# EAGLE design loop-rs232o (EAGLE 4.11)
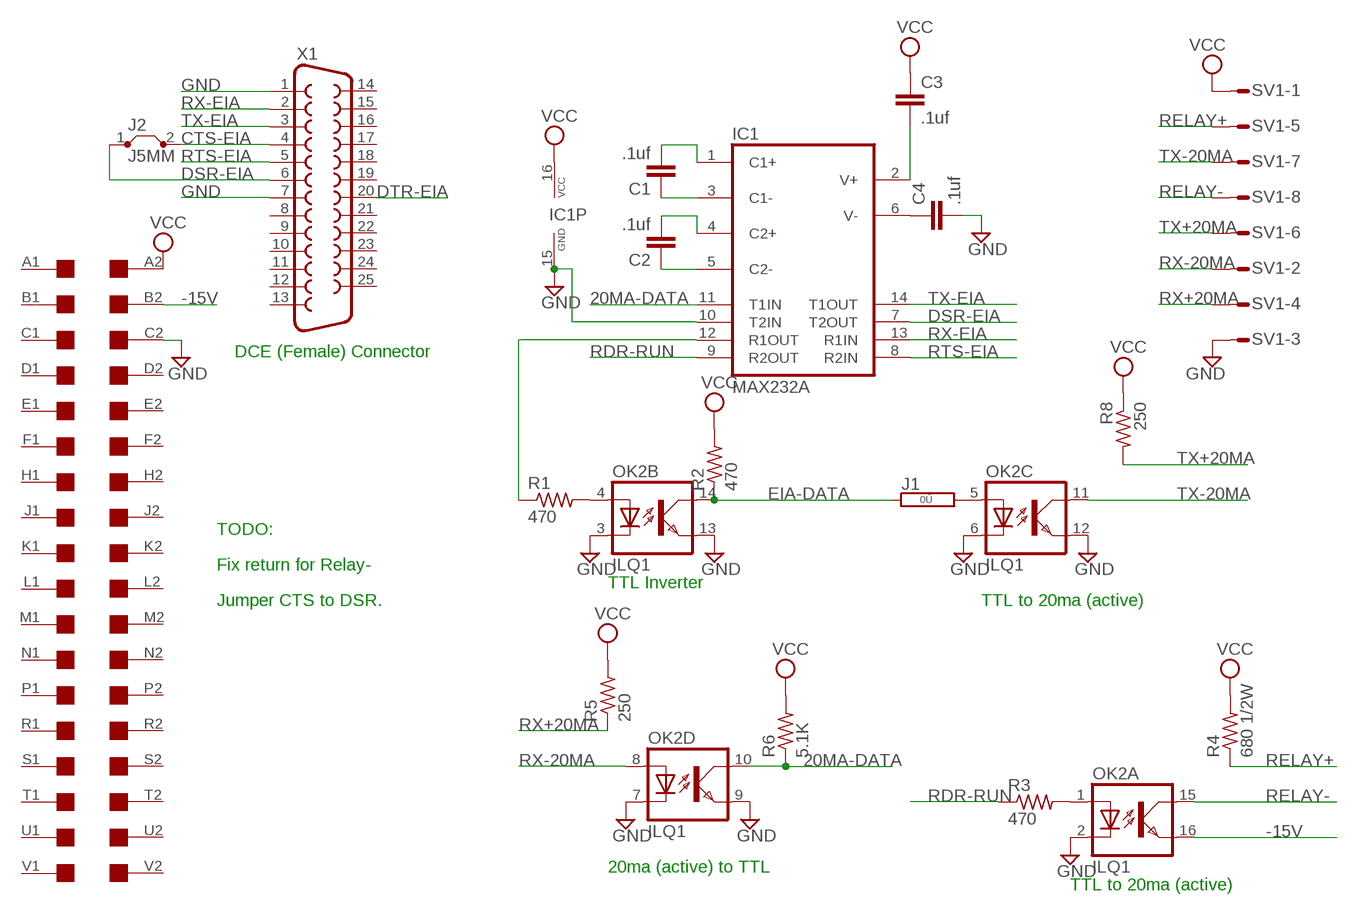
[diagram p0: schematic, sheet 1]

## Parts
C1  .1uf  C-EU050-025X075  [C050-025X075]
C2  .1uf  C-EU050-025X075  [C050-025X075]
C3  .1uf  C-EU050-025X075  [C050-025X075]
C4  .1uf  C-EU050-025X075  [C050-025X075]
IC1  MAX232A  MAX232  [DIL16]
J1  0R  [0R/10]
J2  J5MM  [05]
OK2  ILQ1  [DIL16]
R1  470  R-US_0207/10  [0207/10]
R2  470  R-US_0207/10  [0207/10]
R3  470  R-US_0207/10  [0207/10]
R4  680 1/2W  R-US_0207/10  [0207/10]
R5  250  R-US_0207/10  [0207/10]
R6  5.1K  R-US_0207/10  [0207/10]
R8  250  R-US_0207/10  [0207/10]
SV1  S08P  [S08P]
U$1  DEC-FLIPCHIP  [DEC-FLIPCHIP]
X1  F25H  [F25H]

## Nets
20MA-DATA: IC1.11(T1IN) OK2.10(D:COL) R6.1
-15V: OK2.16(A:EMIT) U$1.B2
CTS-EIA: J2.2 X1.4
DSR-EIA: IC1.7(T2OUT) J2.1 X1.6
DTR-EIA: X1.20
EIA-DATA: J1.1 OK2.14(B:COL) R2.1
GND: C4.2 IC1.10(T2IN) IC1.15(GND) OK2.2(A:C) OK2.3(B:C) OK2.6(C:C) OK2.7(D:C) OK2.9(D:EMIT) OK2.12(C:EMIT) OK2.13(B:EMIT) SV1.3 U$1.C2 X1.1 X1.7
N$1: C2.1 IC1.5(C2-)
N$2: C2.2 IC1.4(C2+)
N$3: C1.2 IC1.1(C1+)
N$4: C1.1 IC1.3(C1-)
N$8: IC1.12(R1OUT) R1.1
N$9: C3.2 IC1.2(V+)
N$10: C4.1 IC1.6(V-)
N$11: OK2.4(B:A) R1.2
N$12: OK2.1(A:A) R3.2
N$15: J1.2 OK2.5(C:A)
RDR-RUN: IC1.9(R2OUT) R3.1
RELAY+: R4.1 SV1.5
RELAY-: OK2.15(A:COL) SV1.8
RTS-EIA: IC1.8(R2IN) X1.5
RX+20MA: R5.1 SV1.4
RX-20MA: OK2.8(D:A) SV1.2
RX-EIA: IC1.13(R1IN) X1.2
TX+20MA: R8.2 SV1.6
TX-20MA: OK2.11(C:COL) SV1.7
TX-EIA: IC1.14(T1OUT) X1.3
VCC: C3.1 IC1.16(VCC) R2.2 R4.2 R5.2 R6.2 R8.1 SV1.1 U$1.A2
Unconnected: U$1.A1 U$1.B1 U$1.C1 U$1.D1 U$1.D2 U$1.E1 U$1.E2 U$1.F1 U$1.F2 U$1.H1 U$1.H2 U$1.J1 U$1.J2 U$1.K1 U$1.K2 U$1.L1 U$1.L2 U$1.M1 U$1.M2 U$1.N1 U$1.N2 U$1.P1 U$1.P2 U$1.R1 U$1.R2 U$1.S1 U$1.S2 U$1.T1 U$1.T2 U$1.U1 U$1.U2 U$1.V1 U$1.V2 X1.8 X1.9 X1.10 X1.11 X1.12 X1.13 X1.14 X1.15 X1.16 X1.17 X1.18 X1.19 X1.21 X1.22 X1.23 X1.24 X1.25

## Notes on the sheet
- DCE (Female) Connector
- TODO:
- Fix return for Relay-
- TTL Inverter
- Jumper CTS to DSR. | TTL to 20ma (active)
- 20ma (active) to TTL
- TTL to 20ma (active)

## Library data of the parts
C1-C4 = rcl:C-EU: CAPACITOR, European symbol
IC1 = maxim:MAX232: RS232 TRANSEIVER
J1 = jumper:0R: Bridge 0R 10mm
J2 = jumper:J: Bridge
OK2 = optocoupler:ILQ1: SIEMENS OPTO COUPLER
R1-R6 R8 = rcl:R-US_: RESISTOR, American symbol
SV1 = con-amp-mt:S08P: AMP MT CONNECTOR
U$1 = con-dec:DEC-FLIPCHIP: DEC Flip-Chip single card fingers
X1 = con-subd:F25: SUB-D

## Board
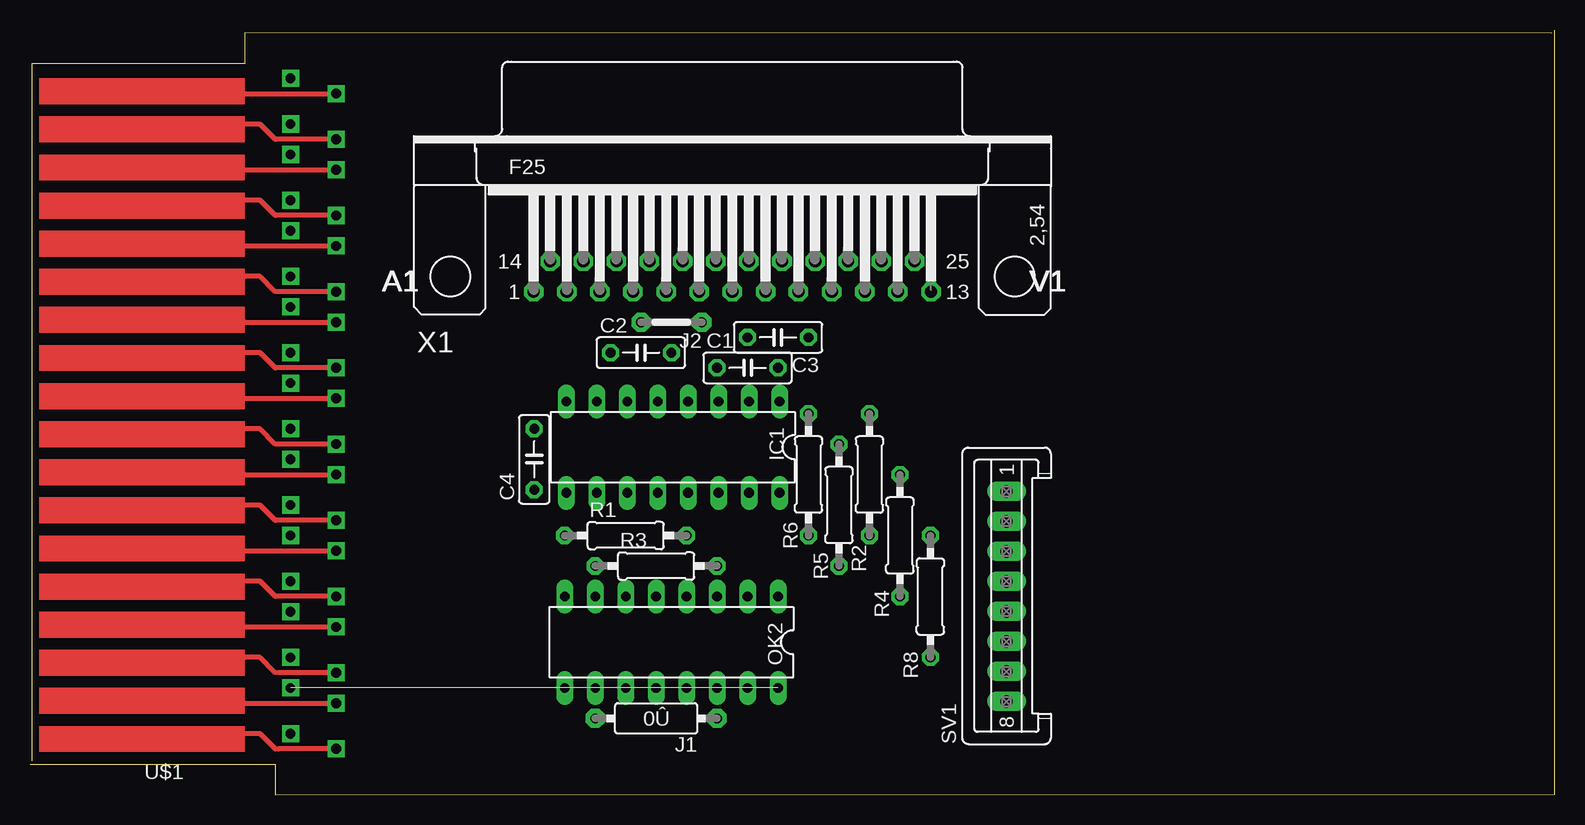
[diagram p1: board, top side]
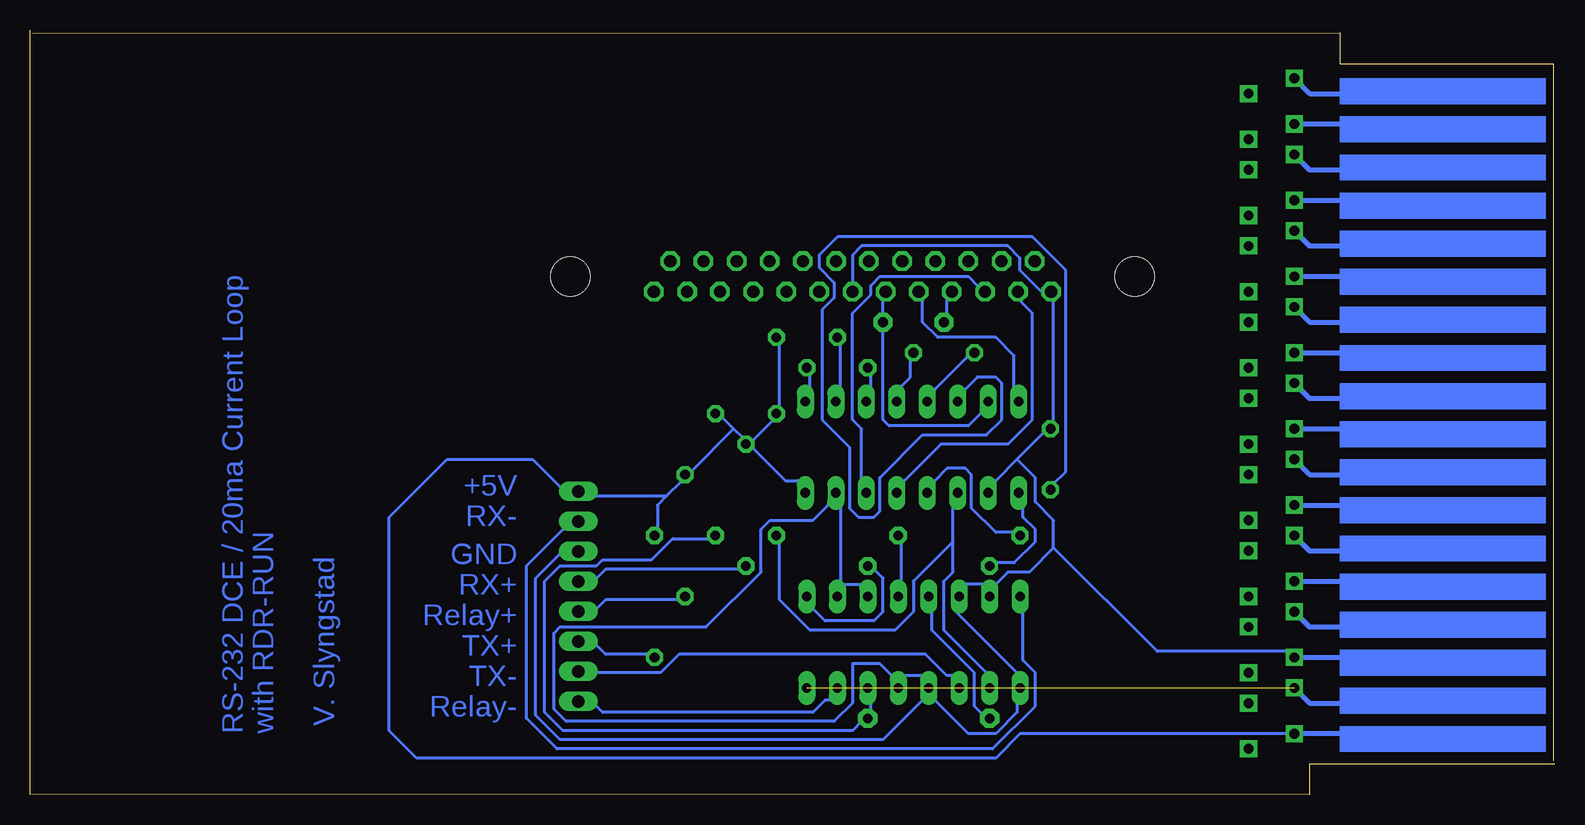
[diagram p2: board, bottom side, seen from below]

Size 127.11 x 63.72 mm. Coordinates in mm from the lower left corner, seen from the top.
Outline: 0,2.54 20.45,2.54 20.45,0 127.11,0.04 127.11,63.72
Outline: 126.87,63.46 17.91,63.5 17.91,60.92 0.13,60.92 0.13,2.83
Copper layers (1*16): Top 0.035mm / dielectric 1.5mm / Bottom 0.035mm
Design rules "10mils": minimum track width 10mil, minimum drill 28mil, track to track 15mil, track to pad 10mil, pad to pad 10mil, via to via 10mil, smd to smd 10mil, copper to edge 40mil, drill to drill 10mil, minimum pad ring 12mil, minimum via ring 8mil, stop-mask expansion 0mil, vias tented up to drill 0mil, thermal gap 10mil

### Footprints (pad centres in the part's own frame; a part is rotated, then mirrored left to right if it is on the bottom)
C050-025X075 = drill 0.813 octagon: 1 -2.54,0; 2 2.54,0
DIL16 = drill 0.813 long: 1 -8.89,-3.81; 2 -6.35,-3.81; 3 -3.81,-3.81; 4 -1.27,-3.81; 5 1.27,-3.81; 6 3.81,-3.81; 7 6.35,-3.81; 8 8.89,-3.81; 9 8.89,3.81; 10 6.35,3.81; 11 3.81,3.81; 12 1.27,3.81; 13 -1.27,3.81; 14 -3.81,3.81; 15 -6.35,3.81; 16 -8.89,3.81
0R/10 = drill 0.813 pad 1.6 octagon: 1 -5.08,0; 2 5.08,0
05 = drill 0.813 pad 1.6 octagon: 1 -2.54,0; 2 2.54,0
0207/10 = drill 0.813 octagon: 1 -5.08,0; 2 5.08,0
S08P = drill 1.016 long: 1 8.75,0; 2 6.25,0; 3 3.75,0; 4 1.25,0; 5 -1.25,0; 6 -3.75,0; 7 -6.25,0; 8 -8.75,0
DEC-FLIPCHIP = drill 0.813 square: A1 -7.62,27.94; A2 -3.81,26.67; B1 -7.62,24.13; B2 -3.81,22.86; C1 -7.62,21.59; C2 -3.81,20.32; D1 -7.62,17.78; D2 -3.81,16.51; E1 -7.62,15.24; E2 -3.81,13.97; F1 -7.62,11.43; F2 -3.81,10.16; H1 -7.62,8.89; H2 -3.81,7.62; J1 -7.62,5.08; J2 -3.81,3.81; K1 -7.62,2.54; K2 -3.81,1.27; L1 -7.62,-1.27; L2 -3.81,-2.54; M1 -7.62,-3.81; M2 -3.81,-5.08; N1 -7.62,-7.62; N2 -3.81,-8.89; P1 -7.62,-10.16; P2 -3.81,-11.43; R1 -7.62,-13.97; R2 -3.81,-15.24; S1 -7.62,-16.51; S2 -3.81,-17.78; T1 -7.62,-20.32; T2 -3.81,-21.59; U1 -7.62,-22.86; U2 -3.81,-24.13; V1 -7.62,-26.67; V2 -3.81,-27.94
F25H = drill 1.016 octagon: 1 -16.561,-1.27; 2 -13.792,-1.27; 3 -11.049,-1.27; 4 -8.28,-1.27; 5 -5.512,-1.27; 6 -2.769,-1.27; 7 0,-1.27; 8 2.769,-1.27; 9 5.512,-1.27; 10 8.28,-1.27; 11 11.049,-1.27; 12 13.792,-1.27; 13 16.561,-1.27; 14 -15.189,1.27; 15 -12.421,1.27; 16 -9.652,1.27; 17 -6.909,1.27; 18 -4.14,1.27; 19 -1.372,1.27; 20 1.372,1.27; 21 4.14,1.27; 22 6.909,1.27; 23 9.652,1.27; 24 12.421,1.27; 25 15.189,1.27 | hole 3.302: -23.52,0; 23.52,0

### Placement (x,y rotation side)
C1  59.82,35.56 0 top
C2  50.93,36.83 0 top
C3  62.36,38.1 180 top
C4  42.04,27.94 90 top
IC1  53.59,28.96 180 top
J1  52.2,6.35 180 top
J2  53.47,39.37 180 top
OK2  53.47,12.7 180 top
R1  49.66,21.59 0 top
R2  69.98,26.67 90 top
R3  52.2,19.05 0 top
R4  72.52,21.59 90 top
R5  67.44,24.13 90 top
R6  64.9,26.67 90 top
R8  75.06,16.51 270 top
SV1  81.41,16.51 90 top
U$1  17.91,31.75 180 top
X1  58.55,43.18 0 top

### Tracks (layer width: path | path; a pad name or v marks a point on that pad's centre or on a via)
20MA-DATA
  Bottom 0.254: 50.16,21.08 50.16,18.54 50.93,17.78 50.93,13.72 47.37,10.16 OK2.10 | 50.16,21.08 50.16,23.88 IC1.11 | 50.16,21.08 53.47,17.78 53.47,15.24 54.99,13.72 62.1,13.72 64.64,16.26 64.64,21.08 R6.1
-15V  (1 unrouted)
CTS-EIA
  Bottom 0.254: J2.2 50.67,40.13 50.67,41.4 X1.4
DSR-EIA
  Bottom 0.254: IC1.7 47.88,31.75 48.9,30.73 55.5,30.73 56.01,31.24 56.01,38.61 J2.1 56.01,41.15 X1.6
EIA-DATA
  Bottom 0.254: OK2.14 57.02,7.62 57.02,6.86 J1.1 57.79,6.1 58.55,5.33 82.68,5.33 84.2,6.86 84.2,17.78 82.93,19.05 79.88,19.05 79.38,19.56 75.31,19.56 73.53,21.34 70.48,21.34 R2.1
GND
  Bottom 0.254: 44.83,27.94 46.61,26.16 IC1.10 | 44.83,27.94 42.55,30.23 C4.2 41.78,30.99 41.78,41.15 X1.1 42.55,41.66 44.58,43.69 44.58,44.7 45.59,45.72 57.79,45.72 58.55,44.96 X1.7 | OK2.3 57.79,17.53 59.31,17.53 OK2.2 59.56,17.78 59.56,23.88 IC1.15 60.58,24.13 61.85,22.86 65.41,22.86 66.17,22.1 66.17,18.54 70.74,13.97 82.93,13.97 83.44,13.46 83.44,7.11 82.42,6.1 60.07,6.1 58.55,7.62 58.55,10.92 56.26,10.92 55.25,9.91 OK2.13 54.23,9.91 52.71,9.91 OK2.12 | SV1.3 82.93,20.07 84.96,18.03 84.96,6.6 82.93,4.57 56.01,4.57 52.71,7.87 OK2.12 | OK2.12 51.69,7.87 48.9,5.08 46.61,5.08 44.83,6.86 44.83,7.62 OK2.9 44.83,10.16 49.91,15.24 OK2.6 49.15,17.53 47.62,17.53 OK2.7 46.61,17.53 45.59,18.54 43.82,18.54 41.78,20.57 | 44.83,27.94 43.31,26.42 43.31,24.38 41.78,22.86 41.78,20.57 | 41.78,20.57 33.15,11.94 22.22,11.94 U$1.C2
N$1
  Bottom 0.254: 52.2,34.04 IC1.5 51.69,33.78 48.9,36.58 C2.1
N$2
  Bottom 0.254: IC1.4 54.48,34.04 53.72,34.8 53.72,36.32 C2.2
N$3
  Bottom 0.254: C1.2 62.1,35.05 62.1,34.04 IC1.1
N$4
  Bottom 0.254: C1.1 57.02,35.05 57.02,34.04 IC1.3
N$8
  Bottom 0.254: R1.1 45.09,21.84 46.61,21.84 48.64,23.88 48.64,26.67 49.15,27.18 50.67,27.18 51.69,26.16 IC1.12
N$9
  Bottom 0.254: C3.2 59.56,37.59 59.56,34.04 IC1.2
N$10
  Bottom 0.254: IC1.6 49.15,33.78 48.13,34.8 46.61,34.8 46.1,34.29 46.1,31.24 47.37,29.97 52.71,29.97 56.26,26.42 56.26,23.62 56.77,23.11 58.04,23.11 58.8,23.88 58.8,28.96 61.09,31.24 61.09,40.39 60.07,41.4 60.07,42.67 61.34,43.94 61.34,44.96 59.82,46.48 43.56,46.48 40.77,43.69 40.77,26.92 41.78,25.91 C4.1
N$11
  Bottom 0.254: R1.2 54.48,21.08 54.48,17.78 OK2.4
N$12
  Bottom 0.254: R3.2 56.77,18.8 56.01,18.03 56.01,15.24 56.77,14.48 60.83,14.48 61.85,15.49 OK2.1
N$15
  Bottom 0.254: OK2.5 51.94,15.24 51.94,13.72 48.39,10.16 48.39,7.37 47.62,6.6 J1.2
RDR-RUN
  Bottom 0.254: IC1.9 44.32,23.88 44.32,23.11 43.31,22.1 43.31,21.08 45.09,19.3 46.61,19.3 R3.1
RELAY+
  Bottom 0.254: R4.1 73.02,16.26 79.12,16.26 79.88,15.49 SV1.5
RELAY-
  Bottom 0.254: OK2.15 60.33,7.87 60.83,7.87 61.85,6.86 79.38,6.86 79.88,7.37 SV1.8
RTS-EIA
  Bottom 0.254: IC1.8 45.09,34.04 45.09,36.58 46.61,38.1 51.44,38.1 52.71,39.37 52.71,41.15 X1.5
RX+20MA
  Bottom 0.254: R5.1 67.94,18.8 79.12,18.8 79.88,18.03 SV1.4
RX-20MA
  Bottom 0.254: OK2.8 44.32,15.24 44.32,11.18 43.31,10.16 43.31,7.37 46.86,3.81 83.19,3.81 85.72,6.35 85.72,19.05 82.68,22.1 SV1.2
RX-EIA
  Bottom 0.254: IC1.13 54.23,26.16 51.18,29.21 45.59,29.21 43.56,31.24 43.56,40.13 44.58,41.15 X1.2
TX+20MA
  Bottom 0.254: R8.2 75.56,11.68 79.12,11.68 79.88,12.45 SV1.6
TX-20MA
  Bottom 0.254: OK2.11 50.16,9.91 50.67,9.91 52.45,11.68 73.02,11.68 74.55,10.16 79.88,10.16 SV1.7
TX-EIA
  Bottom 0.254: IC1.14 57.79,26.42 57.79,30.48 58.55,31.24 58.55,40.13 57.02,41.66 57.02,42.42 56.26,43.18 48.9,43.18 48.13,42.42 X1.3
VCC
  Bottom 0.254: C3.1 64.64,37.59 64.64,32.26 R6.2 65.15,31.24 66.93,29.46 R5.2 | IC1.16 63.12,26.16 64.13,26.16 66.93,28.96 R5.2 | 68.45,30.48 67.69,29.72 R5.2 | 68.45,30.48 69.47,31.5 R2.2 | 68.45,30.48 72.01,26.92 R4.2 72.77,26.16 74.04,24.89 | 74.04,24.89 74.8,24.13 74.8,22.1 R8.1 | 74.04,24.89 79.88,24.89 SV1.1 82.93,25.65 85.22,27.94 92.33,27.94 97.16,23.11 97.16,5.33 94.87,3.05 46.61,3.05 44.58,5.08 U$1.A2

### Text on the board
Bottom: +5V | RX- | GND | RX+ | Relay+ | TX+ | TX- | Relay- | V. Slyngstad | with RDR-RUN | RS-232 DCE / 20ma Current Loop
tNames: A1 | A1 | A1 | A1 | A1 | A1 | A1 | A1 | A1 | A1 | A1 | A1 | A1 | A1 | A1 | A1 | A1 | A1 | A1 | A1 | A1 | A1 | A1 | A1 | A1 | A1 | A1 | A1 | A1 | A1 | A1 | A1 | V1 | V1 | V1 | V1 | V1 | V1 | V1 | V1 | V1 | V1 | V1 | V1 | V1 | V1 | V1 | V1 | V1 | V1 | V1 | V1 | V1 | V1 | V1 | V1 | V1 | V1 | V1 | V1 | V1 | V1 | V1 | V1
